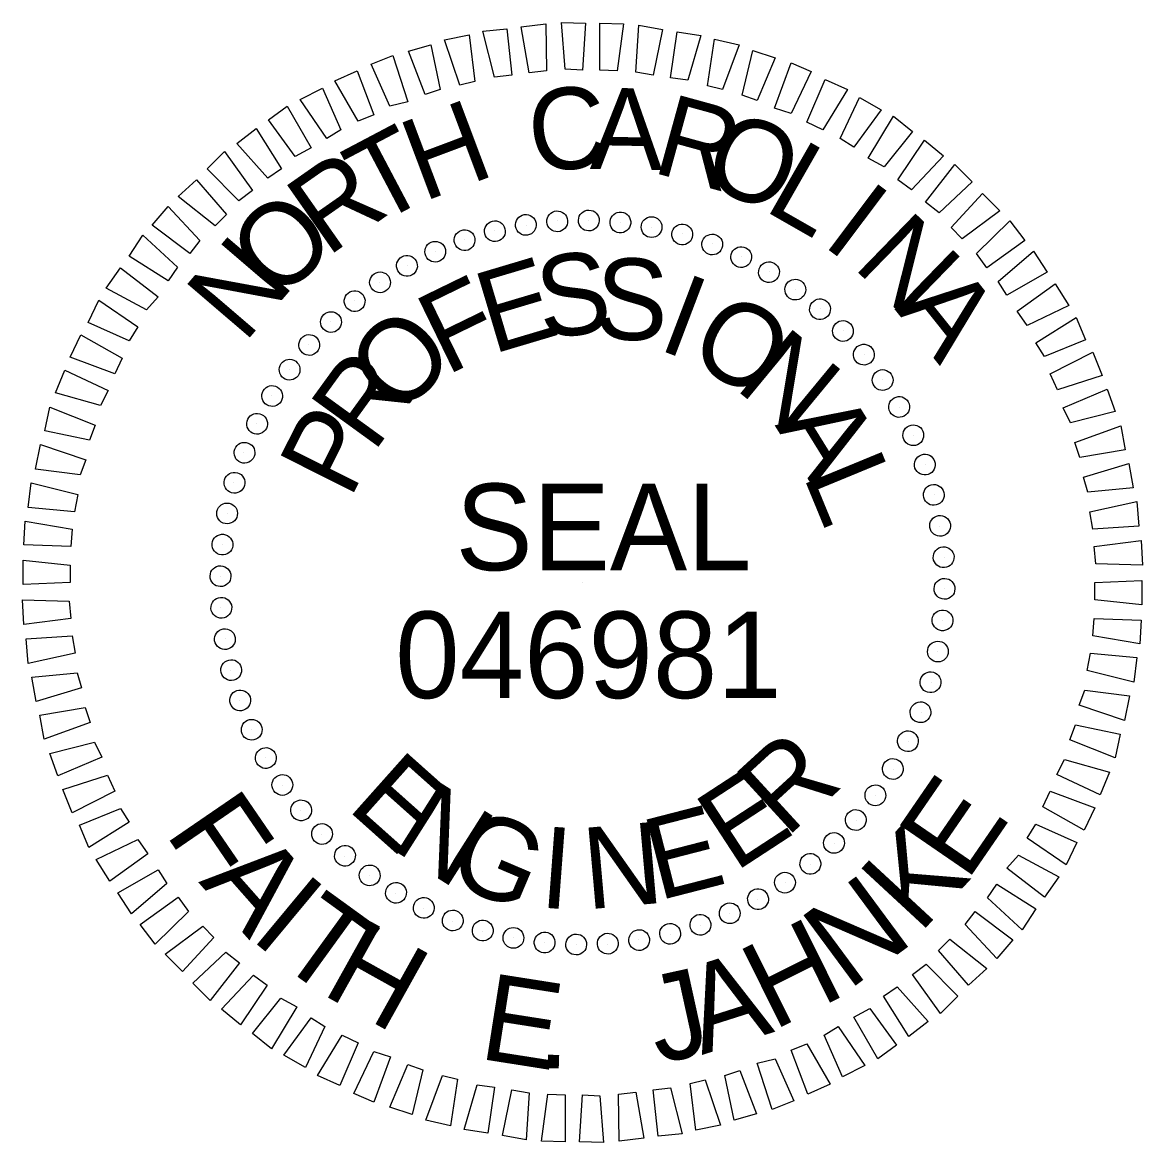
# Model space of a CAD drawing. Extents: x 1184121 to 1184397, y 1246506 to 1246661.
# Drawn here: x 1184372.5 to 1184382.37, y 1246623.86 to 1246633.74 of the extents above; entities that cross this region are included whole.
import ezdxf

# ---------------------------------------------------------------- set-up
doc = ezdxf.new("R2010")
doc.units = 0
doc.layers.add('Sheet PE Seal Cell', color=7, linetype='Continuous')

msp = doc.modelspace()

# ---------------------------------------------------------------- linework, layer by layer
at = {"layer": 'Sheet PE Seal Cell'}
for p, q in [((1184377.2121, 1246631.9909), (1184377.2121, 1246631.9909)), ((1184377.4922, 1246631.9973), (1184377.4922, 1246631.9973)), ((1184377.7723, 1246631.9782), (1184377.7723, 1246631.9782)), ((1184376.6583, 1246631.9018), (1184376.6583, 1246631.9018)), ((1184376.9384, 1246631.9527), (1184376.9384, 1246631.9527)), ((1184378.046, 1246631.9336), (1184378.046, 1246631.9336)), ((1184378.3134, 1246631.8763), (1184378.3134, 1246631.8763)), ((1184376.3909, 1246631.8254), (1184376.3909, 1246631.8254)), ((1184378.5807, 1246631.7872), (1184378.5807, 1246631.7872)), ((1184376.1363, 1246631.7236), (1184376.1363, 1246631.7236)), ((1184378.8354, 1246631.6726), (1184378.8354, 1246631.6726)), ((1184375.888, 1246631.5963), (1184375.888, 1246631.5963)), ((1184379.0836, 1246631.5453), (1184379.0836, 1246631.5453)), ((1184375.6461, 1246631.4498), (1184375.6461, 1246631.4498)), ((1184379.3128, 1246631.3862), (1184379.3128, 1246631.3862)), ((1184375.4233, 1246631.2907), (1184375.4233, 1246631.2907)), ((1184379.5356, 1246631.2143), (1184379.5356, 1246631.2143)), ((1184375.2133, 1246631.0997), (1184375.2133, 1246631.0997)), ((1184379.7329, 1246631.0233), (1184379.7329, 1246631.0233)), ((1184375.0223, 1246630.9024), (1184375.0223, 1246630.9024)), ((1184379.9239, 1246630.8133), (1184379.9239, 1246630.8133)), ((1184374.8504, 1246630.6796), (1184374.8504, 1246630.6796)), ((1184380.083, 1246630.5905), (1184380.083, 1246630.5905)), ((1184374.6913, 1246630.4504), (1184374.6913, 1246630.4504)), ((1184380.2294, 1246630.3486), (1184380.2294, 1246630.3486)), ((1184374.564, 1246630.2022), (1184374.564, 1246630.2022)), ((1184380.3568, 1246630.1003), (1184380.3568, 1246630.1003)), ((1184374.4494, 1246629.9475), (1184374.4494, 1246629.9475)), ((1184380.4586, 1246629.8457), (1184380.4586, 1246629.8457)), ((1184374.3603, 1246629.6802), (1184374.3603, 1246629.6802)), ((1184380.535, 1246629.5783), (1184380.535, 1246629.5783)), ((1184374.303, 1246629.4128), (1184374.303, 1246629.4128)), ((1184380.5859, 1246629.2982), (1184380.5859, 1246629.2982)), ((1184374.2584, 1246629.1391), (1184374.2584, 1246629.1391)), ((1184380.6241, 1246629.0245), (1184380.6241, 1246629.0245)), ((1184374.2393, 1246628.859), (1184374.2393, 1246628.859)), ((1184377.4349, 1246628.8017), (1184377.4349, 1246628.8017)), ((1184380.6305, 1246628.7444), (1184380.6305, 1246628.7444)), ((1184374.2457, 1246628.5789), (1184374.2457, 1246628.5789)), ((1184380.6114, 1246628.4643), (1184380.6114, 1246628.4643)), ((1184374.2839, 1246628.3052), (1184374.2839, 1246628.3052)), ((1184380.5668, 1246628.1906), (1184380.5668, 1246628.1906)), ((1184374.3348, 1246628.0251), (1184374.3348, 1246628.0251)), ((1184380.5095, 1246627.9232), (1184380.5095, 1246627.9232)), ((1184374.4112, 1246627.7577), (1184374.4112, 1246627.7577)), ((1184380.4204, 1246627.6559), (1184380.4204, 1246627.6559)), ((1184374.513, 1246627.5031), (1184374.513, 1246627.5031)), ((1184380.3058, 1246627.4012), (1184380.3058, 1246627.4012)), ((1184374.6404, 1246627.2548), (1184374.6404, 1246627.2548)), ((1184380.1785, 1246627.153), (1184380.1785, 1246627.153)), ((1184374.7868, 1246627.0129), (1184374.7868, 1246627.0129)), ((1184380.0194, 1246626.9238), (1184380.0194, 1246626.9238)), ((1184374.9459, 1246626.7901), (1184374.9459, 1246626.7901)), ((1184379.8475, 1246626.701), (1184379.8475, 1246626.701)), ((1184375.1369, 1246626.5801), (1184375.1369, 1246626.5801)), ((1184379.6565, 1246626.5037), (1184379.6565, 1246626.5037)), ((1184375.3342, 1246626.3891), (1184375.3342, 1246626.3891)), ((1184379.4465, 1246626.3127), (1184379.4465, 1246626.3127)), ((1184375.557, 1246626.2172), (1184375.557, 1246626.2172)), ((1184379.2237, 1246626.1536), (1184379.2237, 1246626.1536)), ((1184375.7862, 1246626.0581), (1184375.7862, 1246626.0581)), ((1184376.0344, 1246625.9308), (1184376.0344, 1246625.9308)), ((1184378.9818, 1246626.0072), (1184378.9818, 1246626.0072)), ((1184378.7335, 1246625.8798), (1184378.7335, 1246625.8798)), ((1184376.2891, 1246625.8162), (1184376.2891, 1246625.8162)), ((1184378.4789, 1246625.778), (1184378.4789, 1246625.778)), ((1184376.5564, 1246625.7271), (1184376.5564, 1246625.7271)), ((1184376.8238, 1246625.6698), (1184376.8238, 1246625.6698)), ((1184377.9314, 1246625.6507), (1184377.9314, 1246625.6507)), ((1184378.2115, 1246625.7016), (1184378.2115, 1246625.7016)), ((1184377.0975, 1246625.6252), (1184377.0975, 1246625.6252)), ((1184377.3776, 1246625.6061), (1184377.3776, 1246625.6061)), ((1184377.6577, 1246625.6125), (1184377.6577, 1246625.6125))]:
    msp.add_line(p, q, dxfattribs=at)
for points in [[(1184377.2821, 1246633.3277), (1184377.2503, 1246633.7415), (1184377.4604, 1246633.7351), (1184377.4349, 1246633.3214)], [(1184377.5877, 1246633.3214), (1184377.5877, 1246633.7351), (1184377.7977, 1246633.7288), (1184377.7405, 1246633.315)], [(1184376.6583, 1246633.2577), (1184376.5564, 1246633.6651), (1184376.7665, 1246633.6842), (1184376.8111, 1246633.2768)], [(1184376.9638, 1246633.2959), (1184376.8938, 1246633.7033), (1184377.1102, 1246633.7288), (1184377.1166, 1246633.315)], [(1184377.906, 1246633.3023), (1184377.9314, 1246633.716), (1184378.1415, 1246633.6778), (1184378.0587, 1246633.2768)], [(1184378.2115, 1246633.2513), (1184378.2688, 1246633.6587), (1184378.4789, 1246633.6269), (1184378.3643, 1246633.2322)], [(1184376.0472, 1246633.1049), (1184375.9008, 1246633.4869), (1184376.0981, 1246633.5442), (1184376.1809, 1246633.1495)], [(1184376.3527, 1246633.1877), (1184376.219, 1246633.5887), (1184376.4355, 1246633.6333), (1184376.4864, 1246633.2195)], [(1184378.5362, 1246633.1813), (1184378.5998, 1246633.5951), (1184378.8163, 1246633.5442), (1184378.6698, 1246633.1495)], [(1184375.7353, 1246633.0031), (1184375.5697, 1246633.3723), (1184375.7607, 1246633.4487), (1184375.8944, 1246633.0413)], [(1184378.8417, 1246633.0986), (1184378.9372, 1246633.4932), (1184379.1345, 1246633.4296), (1184378.9754, 1246633.054)], [(1184379.1282, 1246632.984), (1184379.2746, 1246633.385), (1184379.4528, 1246633.3086), (1184379.2746, 1246632.9394)], [(1184375.4552, 1246632.8694), (1184375.2515, 1246633.2259), (1184375.4488, 1246633.315), (1184375.5952, 1246632.9267)], [(1184375.1814, 1246632.7166), (1184374.9459, 1246633.0604), (1184375.1432, 1246633.1622), (1184375.3024, 1246632.793)], [(1184379.4146, 1246632.863), (1184379.5738, 1246633.2386), (1184379.7711, 1246633.1495), (1184379.5547, 1246632.793)], [(1184379.7075, 1246632.7166), (1184379.8793, 1246633.0795), (1184380.0703, 1246632.9712), (1184379.8284, 1246632.6402)], [(1184374.9013, 1246632.5575), (1184374.6658, 1246632.8821), (1184374.8313, 1246633.0031), (1184375.0414, 1246632.6339)], [(1184379.9557, 1246632.5447), (1184380.1785, 1246632.914), (1184380.344, 1246632.7803), (1184380.0958, 1246632.4684)], [(1184374.6594, 1246632.3665), (1184374.3857, 1246632.6721), (1184374.5576, 1246632.8057), (1184374.7804, 1246632.4493)], [(1184380.2167, 1246632.3538), (1184380.4522, 1246632.7039), (1184380.6178, 1246632.5638), (1184380.3377, 1246632.2647)], [(1184374.4048, 1246632.1692), (1184374.1247, 1246632.4493), (1184374.2775, 1246632.602), (1184374.5258, 1246632.2583)], [(1184380.4586, 1246632.1564), (1184380.7196, 1246632.4875), (1184380.8724, 1246632.3347), (1184380.5796, 1246632.0609)], [(1184374.1948, 1246631.9464), (1184373.8701, 1246632.2074), (1184374.0292, 1246632.3538), (1184374.2966, 1246632.0482)], [(1184380.6878, 1246631.9336), (1184380.9615, 1246632.2328), (1184381.1143, 1246632.08), (1184380.7833, 1246631.8318)], [(1184373.972, 1246631.7045), (1184373.6409, 1246631.9527), (1184373.781, 1246632.1182), (1184374.0611, 1246631.8191)], [(1184380.9106, 1246631.7045), (1184381.2034, 1246631.9909), (1184381.3371, 1246631.8191), (1184380.9997, 1246631.5772)], [(1184373.781, 1246631.4626), (1184373.4372, 1246631.679), (1184373.5582, 1246631.8636), (1184373.8637, 1246631.5835)], [(1184381.1016, 1246631.4562), (1184381.4135, 1246631.7236), (1184381.5344, 1246631.539), (1184381.1779, 1246631.3353)], [(1184373.59, 1246631.2079), (1184373.2335, 1246631.3989), (1184373.3608, 1246631.5772), (1184373.6919, 1246631.3225)], [(1184381.2671, 1246631.1952), (1184381.6044, 1246631.4371), (1184381.7254, 1246631.2461), (1184381.3562, 1246631.0679)], [(1184373.4372, 1246630.9342), (1184373.0744, 1246631.0934), (1184373.1699, 1246631.2907), (1184373.5136, 1246631.0552)], [(1184381.4326, 1246630.9151), (1184381.789, 1246631.1379), (1184381.8718, 1246630.9406), (1184381.509, 1246630.7942)], [(1184373.3099, 1246630.6414), (1184372.9152, 1246630.7878), (1184373.0107, 1246630.9851), (1184373.3736, 1246630.7814)], [(1184381.5599, 1246630.6414), (1184381.9355, 1246630.8324), (1184382.0182, 1246630.6287), (1184381.6235, 1246630.5013)], [(1184373.1826, 1246630.3613), (1184372.7879, 1246630.4759), (1184372.8707, 1246630.6732), (1184373.2526, 1246630.495)], [(1184381.6745, 1246630.3422), (1184382.0628, 1246630.5077), (1184382.1328, 1246630.3104), (1184381.7381, 1246630.2085)], [(1184373.0871, 1246630.0557), (1184372.6924, 1246630.1385), (1184372.737, 1246630.3486), (1184373.138, 1246630.1894)], [(1184381.7763, 1246630.0367), (1184382.1837, 1246630.1831), (1184382.2219, 1246629.973), (1184381.8209, 1246629.903)], [(1184373.0044, 1246629.7502), (1184372.6097, 1246629.8011), (1184372.6542, 1246630.0176), (1184373.0553, 1246629.8839)], [(1184381.8527, 1246629.7311), (1184382.2537, 1246629.852), (1184382.2919, 1246629.6356), (1184381.8909, 1246629.5974)], [(1184372.9534, 1246629.4255), (1184372.546, 1246629.4637), (1184372.5715, 1246629.6802), (1184372.9853, 1246629.5783)], [(1184381.91, 1246629.4255), (1184382.3238, 1246629.5147), (1184382.3429, 1246629.2982), (1184381.9355, 1246629.2728)], [(1184372.9216, 1246629.12), (1184372.5078, 1246629.1327), (1184372.5206, 1246629.3428), (1184372.9343, 1246629.2728)], [(1184381.9482, 1246629.12), (1184382.362, 1246629.1709), (1184382.3747, 1246628.9545), (1184381.9609, 1246628.9672)], [(1184372.9152, 1246628.8017), (1184372.5015, 1246628.7826), (1184372.5015, 1246628.999), (1184372.9152, 1246628.9545)], [(1184381.9546, 1246628.8017), (1184382.3683, 1246628.8208), (1184382.3683, 1246628.6044), (1184381.9546, 1246628.6489)], [(1184372.9216, 1246628.4834), (1184372.5078, 1246628.4325), (1184372.4951, 1246628.6489), (1184372.9089, 1246628.6362)], [(1184381.9482, 1246628.4834), (1184382.362, 1246628.4707), (1184382.3492, 1246628.2606), (1184381.9355, 1246628.3306)], [(1184372.9598, 1246628.1779), (1184372.546, 1246628.0887), (1184372.5269, 1246628.3052), (1184372.9343, 1246628.3306)], [(1184381.9164, 1246628.1779), (1184382.3238, 1246628.1397), (1184382.2983, 1246627.9232), (1184381.8845, 1246628.0251)], [(1184373.0171, 1246627.8723), (1184372.6161, 1246627.7514), (1184372.5779, 1246627.9678), (1184372.9789, 1246628.006)], [(1184381.8654, 1246627.8532), (1184382.2601, 1246627.8023), (1184382.2156, 1246627.5859), (1184381.8145, 1246627.7195)], [(1184373.0935, 1246627.5668), (1184372.6861, 1246627.4203), (1184372.6479, 1246627.6304), (1184373.0489, 1246627.7004)], [(1184381.7827, 1246627.5477), (1184382.1774, 1246627.4649), (1184382.1328, 1246627.2548), (1184381.7318, 1246627.414)], [(1184373.1953, 1246627.2612), (1184372.807, 1246627.0957), (1184372.737, 1246627.293), (1184373.1317, 1246627.3949)], [(1184381.6872, 1246627.2421), (1184382.0819, 1246627.1275), (1184381.9991, 1246626.9302), (1184381.6172, 1246627.1084)], [(1184373.3099, 1246626.962), (1184372.9343, 1246626.771), (1184372.8516, 1246626.9747), (1184373.2463, 1246627.1021)], [(1184381.5599, 1246626.962), (1184381.9546, 1246626.8156), (1184381.8591, 1246626.6183), (1184381.4962, 1246626.822)], [(1184373.4372, 1246626.6883), (1184373.0808, 1246626.4655), (1184372.998, 1246626.6628), (1184373.3608, 1246626.8092)], [(1184381.4326, 1246626.6692), (1184381.7954, 1246626.51), (1184381.6999, 1246626.3127), (1184381.3562, 1246626.5482)], [(1184373.6027, 1246626.4082), (1184373.2654, 1246626.1663), (1184373.1444, 1246626.3573), (1184373.5136, 1246626.5355)], [(1184381.2798, 1246626.3955), (1184381.6363, 1246626.2045), (1184381.509, 1246626.0263), (1184381.1779, 1246626.2809)], [(1184373.7682, 1246626.1472), (1184373.4563, 1246625.8798), (1184373.3354, 1246626.0644), (1184373.6919, 1246626.2681)], [(1184381.0888, 1246626.1408), (1184381.4326, 1246625.9244), (1184381.3116, 1246625.7398), (1184381.0061, 1246626.0199)], [(1184373.9592, 1246625.8989), (1184373.6664, 1246625.6125), (1184373.5327, 1246625.7844), (1184373.8701, 1246626.0263)], [(1184380.8978, 1246625.8989), (1184381.2289, 1246625.6507), (1184381.0888, 1246625.4852), (1184380.8087, 1246625.7844)], [(1184374.182, 1246625.6698), (1184373.9083, 1246625.3706), (1184373.7555, 1246625.5234), (1184374.0865, 1246625.7716)], [(1184380.675, 1246625.657), (1184380.9997, 1246625.396), (1184380.8406, 1246625.2496), (1184380.5732, 1246625.5552)], [(1184374.4112, 1246625.447), (1184374.1502, 1246625.116), (1184373.9974, 1246625.2687), (1184374.2902, 1246625.5425)], [(1184374.6531, 1246625.2496), (1184374.4176, 1246624.8995), (1184374.252, 1246625.0396), (1184374.5321, 1246625.3388)], [(1184380.465, 1246625.4342), (1184380.7451, 1246625.1541), (1184380.5923, 1246625.0014), (1184380.344, 1246625.3451)], [(1184380.2104, 1246625.2369), (1184380.4841, 1246624.9313), (1184380.3122, 1246624.7977), (1184380.0894, 1246625.1541)], [(1184374.9141, 1246625.0587), (1184374.6913, 1246624.6895), (1184374.5258, 1246624.8231), (1184374.774, 1246625.1351)], [(1184379.9685, 1246625.0459), (1184380.204, 1246624.7213), (1184380.0385, 1246624.6003), (1184379.8284, 1246624.9695)], [(1184375.1623, 1246624.8868), (1184374.9905, 1246624.5239), (1184374.7995, 1246624.6322), (1184375.0414, 1246624.9632)], [(1184379.6884, 1246624.8868), (1184379.9239, 1246624.543), (1184379.7266, 1246624.4412), (1184379.5674, 1246624.8104)], [(1184375.4552, 1246624.7404), (1184375.296, 1246624.3648), (1184375.0987, 1246624.4539), (1184375.3151, 1246624.8104)], [(1184375.7416, 1246624.6194), (1184375.5952, 1246624.2184), (1184375.417, 1246624.2948), (1184375.5952, 1246624.664)], [(1184379.4146, 1246624.734), (1184379.6183, 1246624.3775), (1184379.421, 1246624.2884), (1184379.2746, 1246624.6767)], [(1184376.0281, 1246624.5048), (1184375.9326, 1246624.1102), (1184375.7353, 1246624.1738), (1184375.8944, 1246624.5494)], [(1184379.1345, 1246624.6003), (1184379.3001, 1246624.2311), (1184379.1091, 1246624.1547), (1184378.9754, 1246624.5621)], [(1184376.3336, 1246624.4221), (1184376.27, 1246624.0083), (1184376.0535, 1246624.0592), (1184376.2, 1246624.4539)], [(1184378.8226, 1246624.4985), (1184378.969, 1246624.1165), (1184378.7717, 1246624.0592), (1184378.6889, 1246624.4539)], [(1184376.6583, 1246624.3521), (1184376.601, 1246623.9447), (1184376.3909, 1246623.9765), (1184376.5055, 1246624.3712)], [(1184378.5171, 1246624.4157), (1184378.6508, 1246624.0147), (1184378.4343, 1246623.9701), (1184378.3834, 1246624.3839)], [(1184376.9638, 1246624.3011), (1184376.9384, 1246623.8874), (1184376.7283, 1246623.9256), (1184376.8111, 1246624.3266)], [(1184377.2821, 1246624.282), (1184377.2821, 1246623.8683), (1184377.0721, 1246623.8746), (1184377.1293, 1246624.2884)], [(1184377.5877, 1246624.2757), (1184377.6195, 1246623.8619), (1184377.4094, 1246623.8683), (1184377.4349, 1246624.282)], [(1184377.906, 1246624.3075), (1184377.976, 1246623.9001), (1184377.7596, 1246623.8746), (1184377.7532, 1246624.2884)], [(1184378.2115, 1246624.3457), (1184378.3134, 1246623.9383), (1184378.1033, 1246623.9192), (1184378.0587, 1246624.3266)]]:
    msp.add_lwpolyline(points, close=True, dxfattribs=at)
for centre, major_axis in [((1184377.2122, 1246631.987), (-0.0064, 0.0914)), ((1184377.4906, 1246631.9943), (0.0016, 0.0917)), ((1184377.7687, 1246631.9773), (0.0096, 0.0912)), ((1184376.6624, 1246631.8999), (-0.0222, 0.0889)), ((1184376.9354, 1246631.9554), (-0.0143, 0.0905)), ((1184378.0442, 1246631.9361), (0.0175, 0.09)), ((1184378.315, 1246631.8711), (0.0253, 0.0881)), ((1184376.3953, 1246631.8208), (-0.0298, 0.0867)), ((1184378.5792, 1246631.7827), (0.0329, 0.0856)), ((1184376.1362, 1246631.7187), (-0.0373, 0.0837)), ((1184378.8346, 1246631.6716), (0.0402, 0.0824)), ((1184375.8869, 1246631.5944), (-0.0444, 0.0802)), ((1184379.0794, 1246631.5387), (0.0472, 0.0786)), ((1184375.6494, 1246631.4489), (-0.0513, 0.076)), ((1184379.3117, 1246631.3849), (0.0539, 0.0742)), ((1184375.4255, 1246631.2832), (-0.0577, 0.0712)), ((1184379.5297, 1246631.2115), (0.0601, 0.0692)), ((1184375.2168, 1246631.0986), (-0.0637, 0.0659)), ((1184379.7318, 1246631.0198), (0.0659, 0.0637)), ((1184375.0251, 1246630.8965), (-0.0692, 0.0601)), ((1184379.9164, 1246630.8111), (0.0712, 0.0577)), ((1184374.8517, 1246630.6785), (-0.0742, 0.0539)), ((1184380.0821, 1246630.5872), (0.076, 0.0513)), ((1184374.6979, 1246630.4462), (-0.0786, 0.0472)), ((1184380.2276, 1246630.3497), (0.0802, 0.0444)), ((1184374.565, 1246630.2014), (-0.0824, 0.0402)), ((1184380.3519, 1246630.1004), (0.0837, 0.0373)), ((1184374.4539, 1246629.946), (-0.0856, 0.0329)), ((1184380.454, 1246629.8413), (0.0867, 0.0298)), ((1184374.3656, 1246629.6818), (-0.0881, 0.0253)), ((1184380.5331, 1246629.5742), (0.0889, 0.0222)), ((1184374.3005, 1246629.411), (-0.09, 0.0175)), ((1184380.5886, 1246629.3012), (0.0905, 0.0143)), ((1184374.2593, 1246629.1355), (-0.0912, 0.0096)), ((1184380.6202, 1246629.0244), (0.0914, 0.0064)), ((1184374.2423, 1246628.8574), (-0.0917, 0.0016)), ((1184380.6275, 1246628.746), (0.0917, -0.0016)), ((1184374.2496, 1246628.579), (-0.0914, -0.0064)), ((1184380.6105, 1246628.4679), (0.0912, -0.0096)), ((1184374.2812, 1246628.3022), (-0.0905, -0.0143)), ((1184380.5693, 1246628.1924), (0.09, -0.0175)), ((1184374.3367, 1246628.0292), (-0.0889, -0.0222)), ((1184380.5042, 1246627.9216), (0.0881, -0.0253)), ((1184374.4158, 1246627.7621), (-0.0867, -0.0298)), ((1184380.4159, 1246627.6574), (0.0856, -0.0329)), ((1184374.5179, 1246627.503), (-0.0837, -0.0373)), ((1184380.3048, 1246627.402), (0.0824, -0.0402)), ((1184374.6422, 1246627.2537), (-0.0802, -0.0444)), ((1184380.1719, 1246627.1572), (0.0786, -0.0472)), ((1184374.7877, 1246627.0162), (-0.076, -0.0513)), ((1184380.0181, 1246626.9249), (0.0742, -0.0539)), ((1184374.9534, 1246626.7923), (-0.0712, -0.0577)), ((1184379.8447, 1246626.7069), (0.0692, -0.0601)), ((1184375.138, 1246626.5836), (-0.0659, -0.0637)), ((1184379.653, 1246626.5048), (0.0637, -0.0659)), ((1184375.3401, 1246626.3919), (-0.0601, -0.0692)), ((1184379.4443, 1246626.3202), (0.0577, -0.0712)), ((1184375.5581, 1246626.2185), (-0.0539, -0.0742)), ((1184379.2204, 1246626.1546), (0.0513, -0.076)), ((1184375.7904, 1246626.0647), (-0.0472, -0.0786)), ((1184376.0352, 1246625.9318), (-0.0402, -0.0824)), ((1184378.9829, 1246626.009), (0.0444, -0.0802)), ((1184378.7336, 1246625.8847), (0.0373, -0.0837)), ((1184376.2906, 1246625.8207), (-0.0329, -0.0856)), ((1184376.5548, 1246625.7324), (-0.0253, -0.0881)), ((1184378.4745, 1246625.7826), (0.0298, -0.0867)), ((1184376.8256, 1246625.6673), (-0.0175, -0.09)), ((1184377.9344, 1246625.648), (0.0143, -0.0905)), ((1184378.2074, 1246625.7035), (0.0222, -0.0889)), ((1184377.1011, 1246625.6262), (-0.0096, -0.0912)), ((1184377.3792, 1246625.6091), (-0.0016, -0.0917)), ((1184377.6576, 1246625.6164), (0.0064, -0.0914))]:
    msp.add_ellipse(centre, major_axis=major_axis, ratio=0.999708, dxfattribs=at)

# ---------------------------------------------------------------- texts
for s, height, rotation, p in [('C', 0.7182, 6.21987, (1184376.9957, 1246632.4111)), ('A', 0.7178, 359.02032, (1184377.4986, 1246632.4493)), ('H', 0.7216, 20.61948, (1184376.0281, 1246632.1564)), ('R', 0.7201, 344.6211, (1184378.0333, 1246632.4238)), ('T', 0.7236, 27.81977, (1184375.6143, 1246631.9464)), ('O', 0.7221, 337.42116, (1184378.4598, 1246632.3283)), ('L', 0.7241, 330.22088, (1184379.02, 1246632.0928)), ('R', 0.7252, 35.02051, (1184375.1814, 1246631.6663)), ('I', 0.7253, 323.02014, (1184379.5356, 1246631.7872)), ('O', 0.7258, 42.22174, (1184374.7422, 1246631.2716)), ('N', 0.7259, 315.81891, (1184379.8093, 1246631.5899)), ('N', 0.7255, 49.4235, (1184374.4494, 1246630.9024)), ('E', 0.7205, 16.61107, (1184376.6392, 1246630.8133)), ('S', 0.7183, 7.25561, (1184377.0784, 1246630.9469)), ('S', 0.7178, 357.9004, (1184377.5368, 1246630.9533)), ('F', 0.723, 25.96703, (1184376.2318, 1246630.6223)), ('I', 0.7216, 339.1896, (1184378.0842, 1246630.8642)), ('A', 0.7253, 308.61715, (1184380.1849, 1246631.2143)), ('O', 0.7242, 329.83348, (1184378.3388, 1246630.7751)), ('O', 0.7259, 44.68124, (1184375.8116, 1246630.2467)), ('N', 0.7257, 320.47661, (1184378.7653, 1246630.5204)), ('R', 0.7249, 54.03965, (1184375.5888, 1246629.9348)), ('P', 0.7228, 63.39889, (1184375.3851, 1246629.5274)), ('A', 0.724, 301.76027, (1184379.1282, 1246630.1894)), ('L', 0.7217, 292.40085, (1184379.3764, 1246629.7502)), ('SEAL', 0.76366, 360, (1184376.3147, 1246628.9098)), ('R', 0.7259, 42.48141, (1184379.23, 1246626.5419)), ('E', 0.7257, 318.27689, (1184375.3469, 1246626.8092)), ('E', 0.7248, 33.12409, (1184378.7781, 1246626.2427)), ('N', 0.7247, 327.63396, (1184375.7289, 1246626.4655)), ('E', 0.7708, 55.49302, (1184380.8217, 1246626.1546)), ('F', 0.7708, 304.41424, (1184373.7468, 1246626.5935)), ('E', 0.7199, 14.41176, (1184378.1033, 1246625.9944)), ('G', 0.7223, 336.99024, (1184376.2127, 1246626.179)), ('I', 0.718, 355.7012, (1184377.0466, 1246625.9371)), ('N', 0.7181, 5.05639, (1184377.4731, 1246625.918)), ('K', 0.772, 47.2091, (1184380.405, 1246625.6942)), ('A', 0.7719, 311.43085, (1184374.0442, 1246626.1595)), ('I', 0.772, 320.27116, (1184374.4905, 1246625.6698)), ('N', 0.7716, 36.48327, (1184379.7748, 1246625.1958)), ('T', 0.7716, 324.07311, (1184374.7047, 1246625.4815)), ('H', 0.7701, 330.87335, (1184375.117, 1246625.1816)), ('H', 0.7694, 26.49929, (1184379.1142, 1246624.8447)), ('A', 0.7668, 17.65898, (1184378.4861, 1246624.6336)), ('E', 0.7645, 351.05769, (1184376.5085, 1246624.6041)), ('J', 0.7653, 12.40116, (1184378.0997, 1246624.5548)), ('.', 0.7637, 358.16703, (1184377.0351, 1246624.5217))]:
    msp.add_text(s, height=height, rotation=rotation, dxfattribs=at).set_placement(p)
msp.add_text('046981', height=0.76366, dxfattribs=at).set_placement((1184375.7835, 1246627.7821))

doc.saveas('drawing.dxf')
